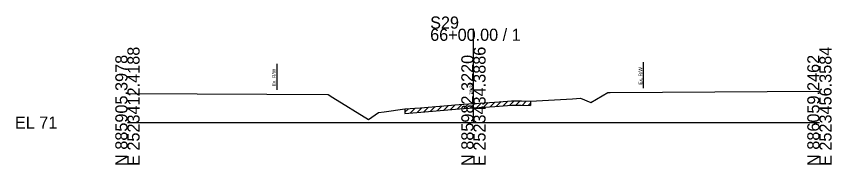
# Model space of a CAD drawing. Extents: x -26 to 163, y -10 to 4024.
# Drawn here: x -25.7 to 162.8, y 3990.3 to 4024.5 of the extents above; entities that cross this region are included whole.
import ezdxf

# ---------------------------------------------------------------- set-up
doc = ezdxf.new("R2010")
doc.units = 0
for name, color, linetype in [('RD_GPK_XS_Cell', 7, 'Continuous'), ('RD_XS_ExGround', 7, 'Continuous'), ('RD_XS_ExPaveRet', 7, 'Continuous'), ('RD_XS_ExRW', 7, 'Continuous'), ('RD_XS_TX_Elev_EX', 7, 'Continuous')]:
    doc.layers.add(name, color=color, linetype=linetype)

msp = doc.modelspace()

# ---------------------------------------------------------------- linework, layer by layer
at = {"layer": 'RD_GPK_XS_Cell'}
for p, q in [((80, 4000), (80, 4021.64)), ((0, 4000), (80, 4000)), ((80, 4000), (160, 4000))]:
    msp.add_line(p, q, dxfattribs=at)
at = {"layer": 'RD_XS_ExGround'}
for p, q in [((0, 4006.73), (32.22, 4006.56)), ((32.22, 4006.56), (46.4, 4006.49)), ((46.4, 4006.49), (47.51, 4005.81)), ((107.11, 4004.62), (111.05, 4006.9)), ((111.05, 4006.9), (111.62, 4006.9)), ((111.62, 4006.9), (160, 4007.21)), ((47.51, 4005.81), (55.72, 4000.71)), ((80, 4004.39), (84.92, 4004.74)), ((84.92, 4004.74), (88.83, 4005.02)), ((88.83, 4005.02), (91.09, 4004.98)), ((91.09, 4004.98), (93.18, 4004.94)), ((93.18, 4004.94), (102.88, 4005.5)), ((102.88, 4005.5), (104.74, 4005.59)), ((104.74, 4005.59), (107.11, 4004.62)), ((59.37, 4002.49), (64.18, 4003.13)), ((64.18, 4003.13), (67.74, 4003.41)), ((67.74, 4003.41), (76.7, 4004.15)), ((76.7, 4004.15), (80, 4004.39)), ((55.72, 4000.71), (58.05, 4002.32)), ((58.05, 4002.32), (59.37, 4002.49))]:
    msp.add_line(p, q, dxfattribs=at)
at = {"layer": 'RD_XS_ExPaveRet'}
for p, q in [((80.8, 4003.44), (81.88, 4004.52)), ((82.33, 4003.55), (83.41, 4004.63)), ((83.85, 4003.66), (84.93, 4004.74)), ((85.37, 4003.77), (86.45, 4004.85)), ((86.89, 4003.88), (87.97, 4004.96)), ((88.42, 4003.98), (89.44, 4005.01)), ((89.84, 4004), (90.83, 4004.98)), ((91.24, 4003.97), (92.22, 4004.96)), ((92.63, 4003.95), (93.18, 4004.5)), ((64.18, 4002.38), (64.99, 4003.19)), ((65.44, 4002.22), (66.53, 4003.31)), ((66.98, 4002.34), (68.07, 4003.43)), ((67.82, 4002.41), (76.77, 4003.15)), ((68.51, 4002.47), (69.61, 4003.56)), ((70.06, 4002.6), (71.15, 4003.69)), ((71.6, 4002.72), (72.69, 4003.82)), ((73.14, 4002.85), (74.24, 4003.95)), ((74.68, 4002.98), (75.78, 4004.08)), ((76.23, 4003.11), (77.31, 4004.2)), ((76.77, 4003.15), (80.07, 4003.39)), ((77.76, 4003.23), (78.84, 4004.31)), ((79.28, 4003.33), (80.36, 4004.41)), ((80.07, 4003.39), (84.99, 4003.74)), ((84.99, 4003.74), (88.86, 4004.02)), ((88.86, 4004.02), (91.07, 4003.98)), ((91.07, 4003.98), (93.18, 4003.94)), ((64.18, 4002.12), (67.82, 4002.41))]:
    msp.add_line(p, q, dxfattribs=at)
for points in [[(93.18, 4004.94), (93.18, 4003.94)], [(64.18, 4003.13), (64.18, 4002.12)]]:
    msp.add_lwpolyline(points, dxfattribs=at)
at = {"layer": 'RD_XS_ExRW'}
for p, q in [((119.27, 4013.95), (119.27, 4007.95)), ((34.55, 4013.55), (34.55, 4007.55))]:
    msp.add_line(p, q, dxfattribs=at)

# ---------------------------------------------------------------- texts
at = {"layer": 'RD_GPK_XS_Cell'}
for s, p in [('S29', (70, 4021.64)), ('66+00.00 / 1', (70, 4018.84)), ('EL 71', (-26, 3998.6))]:
    msp.add_text(s, height=2.8, dxfattribs=at).set_placement(p)
for s, p in [('E 2523412.4188', (2.8, 3990)), ('E 2523434.3886', (82.8, 3990)), ('E 2523456.3584', (162.8, 3990)), ('N 885905.3978', (0, 3990)), ('N 885982.3220', (80, 3990)), ('N 886059.2462', (160, 3990))]:
    msp.add_text(s, height=2.8, rotation=90, dxfattribs=at).set_placement(p)
at = {"layer": 'RD_XS_ExRW'}
for p in [(34.3, 4008.34), (119.02, 4008.74)]:
    msp.add_text('Ex. R/W ', height=0.8, rotation=90, dxfattribs=at).set_placement(p)
at = {"layer": 'RD_XS_TX_Elev_EX'}
msp.add_text('75.39', height=0.8, rotation=90, dxfattribs=at).set_placement((79.9, 4006.39))

doc.saveas('drawing.dxf')
